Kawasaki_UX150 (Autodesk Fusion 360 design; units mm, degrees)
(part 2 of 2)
sketch "Esquisse42" plane through (0, 0, 1860) normal (0, 0, -1) x axis (1, 0, 0)
  line L1 (435, 100) -> (517.3223, 17.6777)
  line L2 (235, 100) -> (435, 100)
  line L3 (152.6777, 17.6777) -> (235, 100)
  line L4 (281.967, -146.967) -> (152.6777, -17.6777)
  line L5 (517.3223, -17.6777) -> (388.033, -146.967)
  line L6 (335, -210) -> (335, 100)
  line L7 (270, -210) -> (335, -210)
  line L8 (400, -210) -> (270, -210)
  line L9 (400, -135) -> (400, -210)
  line L10 (270, -135) -> (400, -135)
  line L11 (270, -210) -> (270, -135)
  line L12 (270, -135) -> (400, -135)
  line L13 (270, -190) -> (270, -135)
  line L14 (400, -190) -> (270, -190)
  line L15 (400, -135) -> (400, -190)
  arc A1 centre (170.3553, 0) radius 25 clockwise from (152.6777, -17.6777) to (152.6777, 17.6777)
  arc A2 centre (335, -93.934) radius 75 clockwise from (388.033, -146.967) to (281.967, -146.967)
  arc A3 centre (499.6447, 0) radius 25 clockwise from (517.3223, 17.6777) to (517.3223, -17.6777)
  point P13 (335, 100)
  point P17 (400, -135)
  point P20 (270, -190)
  point P15 (270, -210)
  point P16 (400, -210)
  midpoint L2 P13
  perpendicular L2 L6
  perpendicular L6 L7
  horizontal L8
  vertical L9
  horizontal L10
  vertical L11
  coincident L5 P17
  horizontal L12
  vertical L13
  horizontal L14
  vertical L15
  coincident L11 P20
  dimension "d247" distance P15 P16 = 130
extrude "Extrusion72" add sketch "Esquisse42" profile of L4 A2 L5 L6 L9 L11 L13 L14 L15 against normal blind 20
sketch "Esquisse43" plane through (0, 0, 1980) normal (0, 0, 1) x axis (-1, 0, 0)
  line L1 (-517.3223, 17.6777) -> (-435, 100)
  line L2 (-388.033, -146.967) -> (-517.3223, -17.6777)
  line L3 (-152.6777, -17.6777) -> (-281.967, -146.967)
  line L4 (-235, 100) -> (-152.6777, 17.6777)
  line L5 (-435, 100) -> (-235, 100)
  line L6 (-335, 0) -> (-335, 100)
  line L7 (-460, -70) -> (-210, -70)
  line L8 (-460, 100) -> (-460, -70)
  line L9 (-210, 100) -> (-460, 100)
  line L10 (-210, -70) -> (-210, 100)
  line L11 (-220, -70) -> (-291.2116, -146.0192)
  line L12 (-450, -70) -> (-378.7884, -146.0192)
  arc A1 centre (-499.6447, 0) radius 25 clockwise from (-517.3223, -17.6777) to (-517.3223, 17.6777)
  arc A2 centre (-335, -93.934) radius 75 clockwise from (-281.967, -146.967) to (-388.033, -146.967)
  arc A3 centre (-170.3553, 0) radius 25 clockwise from (-152.6777, 17.6777) to (-152.6777, -17.6777)
  circle C1 centre (-335, 0) radius 105
  circle C2 centre (-460, 0) radius 45
  circle C3 centre (-210, 0) radius 45
  circle C4 centre (-335, -105) radius 60
  point P13 (-335, 100)
  point P14 (-335, 0)
  point P15 (-335, 0)
  point P20 (-460, 0)
  point P21 (-210, 0)
  point P22 (-335, -105)
  point P23 (-291.2116, -146.0192)
  point P24 (-220, -70)
  point P25 (-378.7884, -146.0192)
  point P26 (-450, -70)
  midpoint L5 P13
  perpendicular L5 L6
  coincident P14 P15
  horizontal L7
  vertical L8
  horizontal L9
  vertical L10
  coincident L8 P20
  coincident L10 P21
  coincident C1 P22
  coincident C4 P23
  tangent C4 L11
  coincident L7 P24
  coincident C4 P25
  tangent C4 L12
  coincident L7 P26
  dimension "d250" diameter C2 = 90
  dimension "d251" diameter C3 = 90
  dimension "d252" diameter C4 = 120
extrude "Extrusion73" cut sketch "Esquisse43" profile of L1 A1 L2 A2 L3 A3 L4 L7 L8 L10 C2 C3 C4 L11 L12 against normal blind 100
sketch "Esquisse44" plane through (335, 0, 0) normal (1, 0, 0) x axis (0, 1, 0)
  line L1 (0, 3220) -> (0, 0)
  line L2 (0, 3030) -> (0, 3220)
  line L3 (0, 3010) -> (0, 3220)
  line L4 (-100, 3010) -> (0, 3010)
  line L5 (-100, 2930) -> (-100, 3010)
  line L6 (-80, 2910) -> (-100, 2930)
  line L7 (0, 2910) -> (-80, 2910)
  line L8 (-70, 2910) -> (0, 2910)
  line L9 (-75, 1975) -> (0, 1975)
  line L10 (-70, 2910) -> (-75, 1975)
  line L11 (-70, 3050) -> (0, 3050)
  line L12 (-70, 3025) -> (-70, 3050)
  line L13 (-95, 3025) -> (-70, 3025)
  line L14 (-100, 3020) -> (-95, 3025)
  line L15 (-100, 3010) -> (-100, 3020)
  line L16 (75, 1975) -> (0, 1975)
  line L17 (70, 2910) -> (0, 2910)
  line L18 (70, 2910) -> (75, 1975)
  line L19 (-100, 2000) -> (0, 2000)
  line L20 (-100, 1980) -> (-100, 2000)
  line L21 (0, 1980) -> (-100, 1980)
  line L22 (99.9986, 2000.5348) -> (0, 2000)
  point P1 (0, 0)
  point P2 (0, 0)
  point P4 (0, 3030)
  point P5 (0, 3010)
  point P9 (0, 2910)
  point P10 (-70, 2910)
  point P11 (0, 1975)
  point P13 (0, 3050)
  point P20 (0, 2000)
  point P23 (0, 1980)
  point P3 (0, 3220)
  point P19 (70, 2910)
  point P24 (99.9986, 2000.5348)
  coincident P1 P2
  vertical L1
  coincident L1 P4
  coincident L1 P5
  perpendicular L1 L4
  perpendicular L4 L5
  coincident L1 P9
  perpendicular L1 L7
  coincident L7 P10
  coincident L1 P11
  perpendicular L1 L9
  coincident L3 P13
  perpendicular L3 L11
  perpendicular L11 L12
  perpendicular L12 L13
  perpendicular L4 L15
  perpendicular L1 L16
  perpendicular L1 L17
  coincident L1 P20
  perpendicular L1 L19
  perpendicular L17 L20
  coincident L1 P23
  perpendicular L1 L21
  perpendicular L18 L22
  dimension "d255" distance P2 P3 = 3220 (= "700 mm + 900 mm + 270 mm + 1350 mm")
  dimension "d257" distance P9 P19 = 70
  dimension "d258" distance P20 P24 = 100
revolve "Révolution5" sketch "Esquisse44" AlongAngle 360
revolve "Révolution6" sketch "Esquisse44" AlongAngle 360
sketch "Esquisse45" plane through (0, 0, 1980) normal (0, 0, 1) x axis (-1, 0, 0)
  line L1 (-460, 45) -> (-460, 75)
  line L2 (-460, -70) -> (-460, -45)
  line L3 (-450, -70) -> (-460, -70)
  line L4 (-378.7884, -146.0192) -> (-450, -70)
  line L5 (-220, -70) -> (-291.2116, -146.0192)
  line L6 (-210, -70) -> (-220, -70)
  line L7 (-210, -45) -> (-210, -70)
  line L8 (-210, 75) -> (-210, 45)
  line L9 (-235, 100) -> (-210, 75)
  line L10 (-335, 100) -> (-235, 100)
  line L11 (-435, 100) -> (-335, 100)
  line L12 (-460, 75) -> (-435, 100)
  line L13 (-235, 100) -> (-235, 0)
  line L14 (-435, 0) -> (-435, 100)
  arc A1 centre (-460, 0) radius 45 clockwise from (-460, -45) to (-460, 45)
  arc A2 centre (-335, -105) radius 60 clockwise from (-291.2116, -146.0192) to (-378.7884, -146.0192)
  arc A3 centre (-210, 0) radius 45 clockwise from (-210, 45) to (-210, -45)
  circle C1 centre (-335, 0) radius 100
  point P21 (-235, 0)
  point P17 (-235, 100)
  point P22 (-235, 100)
  point P20 (-435, 100)
  point P23 (-435, 100)
  point P24 (-435, 0)
  coincident C1 P21
  tangent C1 L13
  coincident P17 P22
  coincident P20 P23
  coincident C1 P24
  tangent C1 L14
extrude "Extrusion74" cut sketch "Esquisse45" profile of L1 A1 L2 L3 L4 A2 L5 L6 L7 A3 L8 L9 C1 L12 L13 L14 against normal blind 50
extrude "Extrusion75" cut of existing geometry blind -10
sketch "Esquisse46" plane through (0, 0, 1860) normal (0, 0, -1) x axis (1, 0, 0)
  line L1 (435, 100) -> (517.3223, 17.6777)
  line L2 (235, 100) -> (435, 100)
  line L3 (152.6777, 17.6777) -> (235, 100)
  line L4 (270, -135) -> (152.6777, -17.6777)
  line L5 (270, -190) -> (270, -135)
  line L6 (400, -190) -> (270, -190)
  line L7 (400, -135) -> (400, -190)
  line L8 (517.3223, -17.6777) -> (400, -135)
  line L9 (335, 90) -> (335, 100)
  line L10 (335, 0) -> (335, 90)
  line L11 (535, 0) -> (400, -135)
  line L12 (460.7538, -74.2462) -> (535, 0)
  line L13 (368.8299, -17.6777) -> (425.3984, -74.2462)
  line L14 (425.3984, 74.2462) -> (368.8299, 17.6777)
  line L15 (460.7538, 74.2462) -> (535, 0)
  arc A1 centre (170.3553, 0) radius 25 clockwise from (152.6777, -17.6777) to (152.6777, 17.6777)
  arc A2 centre (499.6447, 0) radius 25 clockwise from (517.3223, 17.6777) to (517.3223, -17.6777)
  circle C1 centre (335, 0) radius 25
  arc A3 centre (443.0761, -56.5685) radius 25 clockwise from (460.7538, -74.2462) to (425.3984, -74.2462)
  arc A4 centre (386.5076, 0) radius 25 clockwise from (368.8299, -17.6777) to (368.8299, 17.6777)
  arc A5 centre (443.0761, 56.5685) radius 25 clockwise from (425.3984, 74.2462) to (460.7538, 74.2462)
  circle C2 centre (443.0761, 0) radius 50
  point P14 (335, 100)
  point P16 (335, 0)
  point P17 (335, 0)
  point P11 (400, -135)
  point P18 (400, -135)
  point P20 (443.0761, -91.9239)
  point P21 (351.1522, 0)
  point P19 (535, 0)
  midpoint L2 P14
  perpendicular L2 L9
  perpendicular L2 L10
  coincident P16 P17
  coincident P11 P18
  parallel L8 L11
  parallel L11 L12
  perpendicular L8 L13
  perpendicular L13 L14
  perpendicular L14 L15
  coincident P20 L12
  coincident P20 L13
  tangent L12 A3
  tangent L13 A3
  coincident P21 L13
  coincident P21 L14
  tangent L13 A4
  tangent L14 A4
  equal A3 A4
  tangent L14 A5
  tangent L15 A5
  equal A3 A5
  dimension "d264" distance P19 P20 = 130
  dimension "d265" distance P20 P21 = 130
  dimension "d266" radius A3 = 25
  dimension "d267" diameter C2 = 100
extrude "Extrusion76" new body sketch "Esquisse46" profile of C2 along normal blind 220
extrude "Extrusion77" add sketch "Esquisse46" profile of L1 L8 A2 L11 L12 L13 L14 L15 A3 A4 A5 C2 along normal blind 170
circular_pattern "Réseau C" TotalAngle 180
combine "Combiner11"
sketch "Esquisse47" plane through (0, 0, 0) normal (1, 0, 0) x axis (0, 1, 0)
  line L1 (-200, 1660) -> (-120, 1660)
  line L2 (-200, 1750) -> (-200, 1660)
  line L3 (-170, 1780) -> (-200, 1750)
  line L4 (-170, 1830) -> (-170, 1780)
  line L5 (190.7691, 1975) -> (-25, 1975)
  line L6 (190.7691, 1920) -> (190.7691, 1975)
  line L7 (-35, 1920) -> (190.7691, 1920)
  line L8 (-120, 1660) -> (-120, 1835)
  arc A1 centre (-35, 1835) radius 85 clockwise from (-120, 1835) to (-35, 1920)
  arc A2 centre (-25, 1830) radius 145 clockwise from (-170, 1830) to (-25, 1975)
  horizontal L1
  perpendicular L1 L2
  parallel L2 L4
  perpendicular L4 L5
  perpendicular L5 L6
  perpendicular L6 L7
  perpendicular L1 L8
  tangent L7 A1
  tangent L8 A1
  tangent L5 A2
  tangent L4 A2
  dimension "d274" radius A1 = 85
  dimension "d275" radius A2 = 145
extrude "Extrusion78" new body sketch "Esquisse47" against normal blind 400
extrude "Extrusion79" add of existing geometry blind 200
sketch "Esquisse48" plane through (0, 0, 0) normal (0, 0, 1) x axis (1, 0, 0)
  line L1 (-100, -125) -> (0, -150)
  line L2 (-200, -125) -> (-100, -125)
  line L3 (-200, 175) -> (-200, -125)
  line L4 (-175, 200) -> (-200, 175)
  line L5 (-175, 275) -> (-175, 200)
  line L6 (-250, 275) -> (-175, 275)
  line L7 (-250, -175) -> (-250, 275)
  line L8 (-150, -175) -> (-250, -175)
  line L9 (-100, -190) -> (-150, -175)
  line L10 (0, -190) -> (-100, -190)
  line L11 (0, -150) -> (0, -190)
  horizontal L2
  perpendicular L2 L3
  perpendicular L2 L5
  perpendicular L3 L6
  perpendicular L6 L7
  perpendicular L7 L8
  perpendicular L7 L10
  perpendicular L10 L11
extrude "Extrusion80" new body sketch "Esquisse48" along normal blind 2500
sketch "Esquisse49" plane through (0, 0, 0) normal (0, 1, 0) x axis (1, 0, 0)
  line L1 (-240, -1800) -> (-240, -1990)
  line L2 (-240, -1830) -> (-240, -1800)
  line L3 (0, -1660) -> (-70, -1660)
  line L4 (0, -1780) -> (0, -1660)
  line L5 (-110, -1780) -> (0, -1780)
  line L6 (-200, -1780) -> (-190, -1780)
  line L7 (-200, -1990) -> (-200, -1870)
  line L8 (-240, -1990) -> (-200, -1990)
  arc A1 centre (-70, -1830) radius 170 clockwise from (-240, -1830) to (-70, -1660)
  arc A2 centre (-110, -1870) radius 90 clockwise from (-200, -1870) to (-110, -1780)
  point P6 (-190, -1780)
  point P7 (-200, -1780)
  vertical L1
  parallel L1 L2
  perpendicular L2 L3
  perpendicular L3 L4
  perpendicular L4 L5
  perpendicular L4 L6
  perpendicular L6 L7
  perpendicular L1 L8
  tangent L3 A1
  tangent L2 A1
  coincident P6 L5
  coincident P7 L7
  tangent L5 A2
  tangent L7 A2
  dimension "d282" radius A1 = 170
  dimension "d283" radius A2 = 90
extrude "Extrusion81" new body sketch "Esquisse49" profile of L1 L3 L4 L5 L7 L8 A1 A2 along normal blind 600
extrude "Extrusion82" add of existing geometry blind 700
combine "Combiner12"
combine "Combiner13"
sketch "Esquisse50" plane through (0, 0, 1975) normal (0, 0, 1) x axis (-1, 0, 0)
  line L1 (240, 25) -> (240, -190.7691)
  line L2 (200, 25) -> (240, 25)
  line L3 (200, -190.7691) -> (200, 25)
  line L4 (240, -190.7691) -> (200, -190.7691)
  line L5 (70, -190.7691) -> (240, -190.7691)
  line L6 (70, -340) -> (70, -190.7691)
  line L7 (240, -340) -> (70, -340)
  line L8 (240, -190.7691) -> (240, -340)
  line L9 (240, -270) -> (240, -340)
  line L10 (170, -340) -> (240, -340)
  line L11 (240, -270) -> (170, -340)
  line L12 (174.7349, -205.2651) -> (200, -180)
  line L13 (70, -205.2651) -> (174.7349, -205.2651)
  point P2 (240, -190.7691)
  point P6 (240, -190.7691)
  point P10 (240, -270)
  point P11 (170, -340)
  point P12 (200, -180)
  point P14 (70, -205.2651)
  horizontal L5
  vertical L6
  horizontal L7
  vertical L8
  coincident P2 P6
  coincident L8 P10
  coincident L7 P11
  coincident L3 P12
  parallel L11 L12
  coincident L6 P14
  perpendicular L6 L13
extrude "Extrusion83" add sketch "Esquisse50" profile of L4 L5 L6 L7 L8 L11 L12 L13 against normal blind 60
sketch "Esquisse51" plane through (0, 0, 1975) normal (0, 0, 1) x axis (-1, 0, 0)
  line L1 (240, 25) -> (240, -270)
  line L2 (200, 25) -> (240, 25)
  line L3 (200, -190.7691) -> (200, 25)
  line L4 (189.2309, -190.7691) -> (200, -190.7691)
  line L5 (174.7349, -205.2651) -> (189.2309, -190.7691)
  line L6 (70, -205.2651) -> (174.7349, -205.2651)
  line L7 (70, -340) -> (70, -205.2651)
  line L8 (170, -340) -> (70, -340)
  line L9 (240, -270) -> (170, -340)
  line L10 (-380, -230) -> (70, -230)
  line L11 (-380, -330) -> (-380, -230)
  line L12 (70, -330) -> (-380, -330)
  line L13 (70, -230) -> (70, -330)
  line L14 (-290, -330) -> (-380, -330)
  line L15 (-290, -190) -> (-290, -330)
  line L16 (-380, -190) -> (-290, -190)
  line L17 (-380, -330) -> (-380, -190)
  line L18 (-310, -330) -> (-380, -330)
  line L19 (-310, -230) -> (-310, -330)
  line L20 (-380, -230) -> (-310, -230)
  line L21 (-380, -330) -> (-380, -230)
  point P11 (70, -230)
  point P19 (-310, -230)
  horizontal L10
  vertical L11
  horizontal L12
  vertical L13
  coincident L7 P11
  horizontal L14
  vertical L15
  horizontal L16
  vertical L17
  horizontal L18
  vertical L19
  horizontal L20
  vertical L21
  coincident L10 P19
extrude "Extrusion84" add sketch "Esquisse51" profile of L10 L11 L12 L14 L15 L16 L17 L18 L19 L20 L21 against normal blind 125
extrude "Extrusion85" cut of existing geometry blind -75
extrude "Extrusion86" cut of existing geometry blind -10
extrude "Extrusion87" cut sketch "Esquisse51" profile of L10 L15 L16 L17 L20 against normal blind 105
extrude "Extrusion88" add of existing geometry blind 75
sketch "Esquisse52" plane through (0, 0, 0) normal (0, 1, 0) x axis (1, 0, 0)
  line L1 (0, -3220) -> (0, 0)
  line L2 (335, -3220) -> (0, -3220)
  line L3 (335, -3425) -> (335, -3220)
  line L4 (245, -3425) -> (335, -3425)
  line L5 (245, -3269.0535) -> (245, -3425)
  line L6 (245, -3322.5) -> (335, -3322.5)
  circle C1 centre (335, -3220) radius 102.5
  circle C2 centre (335, -3220) radius 87.5
  circle C3 centre (335, -3220) radius 65
  circle C4 centre (335, -3220) radius 45
  point P1 (0, 0)
  point P2 (0, 0)
  point P4 (335, -3220)
  point P5 (335, -3220)
  point P9 (335, -3220)
  point P12 (245, -3269.0535)
  point P13 (335, -3322.5)
  point P14 (245, -3322.5)
  point P3 (0, -3220)
  point P10 (335, -3425)
  point P11 (245, -3425)
  coincident P1 P2
  vertical L1
  perpendicular L1 L2
  coincident P4 P5
  concentric C1 C2
  concentric C1 C3
  concentric C2 C4
  coincident P5 P9
  perpendicular L2 L3
  perpendicular L3 L4
  coincident C1 P12
  perpendicular L2 L5
  midpoint L3 P13
  coincident L5 P14
  tangent C1 L6
  perpendicular L5 L6
  dimension "d300" distance P2 P3 = 3220
  dimension "d301" distance P3 P4 = 335
  dimension "d302" diameter C1 = 205
  dimension "d303" diameter C2 = 175
  dimension "d304" diameter C3 = 130
  dimension "d305" diameter C4 = 90
  dimension "d320" distance P9 P10 = 205
  dimension "d321" distance P10 P11 = 90
extrude "Extrusion89" new body sketch "Esquisse52" profile of C4 against normal blind 150
extrude "Extrusion90" add sketch "Esquisse52" profile of C3 C4 against normal blind 140
extrude "Extrusion91" add sketch "Esquisse52" profile of C2 C3 against normal blind 130
extrude "Extrusion92" add sketch "Esquisse52" profile of C1 C2 against normal blind 110
extrude "Extrusion93" cut of existing geometry blind -70
extrude "Extrusion94" add sketch "Esquisse52" profile of C3 C4 against normal blind 70
extrude "Extrusion95" cut sketch "Esquisse52" profile of C3 C4 against normal blind 40
revolve "Révolution7" sketch "Esquisse52" AlongAngle 360
sketch "Esquisse53" plane through (335, 0, 0) normal (1, 0, 0) x axis (0, 1, 0)
  line L1 (0, 3180) -> (0, 3050)
  line L2 (40, 3180) -> (0, 3180)
  line L3 (40, 3050) -> (40, 3180)
  line L4 (0, 3050) -> (40, 3050)
  vertical L1
  perpendicular L1 L2
  perpendicular L2 L3
  perpendicular L1 L4
revolve "Révolution8" sketch "Esquisse53" AlongAngle 360
work_plane "Plan de construction2" sketch "Esquisse52" AlongDistance 50
cylinder_primitive "CylindrePrimitive" Height 40 Diameter 150
sketch "Esquisse55" plane through (0, 90, 0) normal (0, 1, 0) x axis (-1, 0, 0)
  line L1 (-425, 3345) -> (-335, 3345)
  line L2 (-425, 3288.589) -> (-425, 3345)
  line L3 (-245, 3345) -> (-335, 3345)
  line L4 (-245, 3288.589) -> (-245, 3345)
  line L5 (-245, 3345) -> (-425, 3345)
  line L6 (-245, 3370) -> (-245, 3345)
  line L7 (-425, 3370) -> (-245, 3370)
  line L8 (-425, 3345) -> (-425, 3370)
  line L9 (-395, 3370) -> (-335, 3370)
  line L10 (-395, 3265) -> (-395, 3370)
  line L11 (-275, 3370) -> (-335, 3370)
  line L12 (-275, 3265) -> (-275, 3370)
  circle C1 centre (-335, 3220) radius 75
  circle C2 centre (-335, 3245) radius 100
  point P4 (-335, 3345)
  point P6 (-425, 3288.589)
  point P8 (-245, 3288.589)
  point P12 (-335, 3370)
  point P14 (-395, 3265)
  point P16 (-275, 3265)
  point P5 (-425, 3345)
  point P7 (-245, 3345)
  point P9 (-245, 3345)
  point P11 (-425, 3370)
  point P13 (-395, 3370)
  point P15 (-275, 3370)
  coincident C2 P4
  horizontal L1
  coincident C2 P6
  perpendicular L1 L2
  perpendicular L2 L3
  coincident C2 P8
  perpendicular L1 L4
  horizontal L5
  vertical L6
  horizontal L7
  vertical L8
  midpoint L7 P12
  parallel L7 L9
  coincident C1 P14
  perpendicular L7 L10
  perpendicular L10 L11
  coincident C1 P16
  perpendicular L7 L12
  dimension "d327" diameter C2 = 200
  dimension "d328" distance P4 P5 = 90
  dimension "d329" distance P4 P7 = 90
  dimension "d330" distance P5 P9 = 180
  dimension "d331" distance P5 P11 = 25
  dimension "d332" distance P12 P13 = 60
  dimension "d333" distance P12 P15 = 60
extrude "Extrusion96" add sketch "Esquisse55" profile of C1 C2 L1 L3 L5 L7 L9 L10 L11 L12 against normal blind 40
sketch "Esquisse56" plane through (0, -110, 0) normal (0, -1, 0) x axis (1, 0, 0)
  line L1 (425, 3322.5) -> (335, 3322.5)
  line L2 (425, 3269.0535) -> (425, 3322.5)
  line L3 (245, 3322.5) -> (425, 3322.5)
  line L4 (245, 3342.5) -> (245, 3322.5)
  line L5 (425, 3342.5) -> (245, 3342.5)
  line L6 (425, 3322.5) -> (425, 3342.5)
  line L7 (245, 3269.0535) -> (245, 3322.5)
  circle C1 centre (335, 3220) radius 87.5
  circle C2 centre (335, 3220) radius 102.5
  point P3 (335, 3322.5)
  point P5 (425, 3269.0535)
  point P9 (245, 3269.0535)
  point P4 (425, 3322.5)
  point P6 (245, 3322.5)
  point P8 (425, 3342.5)
  coincident C2 P3
  tangent C2 L1
  horizontal L1
  coincident C2 P5
  perpendicular L1 L2
  horizontal L3
  vertical L4
  horizontal L5
  vertical L6
  coincident C2 P9
  perpendicular L3 L7
  dimension "d336" distance P3 P4 = 90
  dimension "d337" distance P4 P6 = 180
  dimension "d338" distance P4 P8 = 20
extrude "Extrusion97" add sketch "Esquisse56" profile of C2 L1 L2 L3 L4 L5 L6 L7 against normal blind 40
extrude "Extrusion98" add of existing geometry blind 10
extrude "Extrusion99" add of existing geometry blind 10
split "Scinder1"
extrude "Extrusion100" cut of existing geometry blind -30
extrude "Extrusion101" new body sketch "Esquisse52" profile of L2 C4 L3 against normal blind 70
extrude "Extrusion102" add sketch "Esquisse52" profile of L2 C4 L3 along normal blind 40
extrude "Extrusion103" add of existing geometry blind 90
extrude "Extrusion104" add of existing geometry blind 10
split "Scinder2"
component_from_bodies "Corps->Comp1"
combine "Combiner14"
component_from_bodies "Corps->Comp2"
ground "Fixer"
joint "Assembler1" alignAngle 0 alignOffsetX 0 alignOffsetY 0 alignOffsetZ 0 RotationMinimum -180 RotationMaximum 180
component_from_bodies "Corps->Comp3"
joint "Assembler2" alignAngle -0.035 alignOffsetX 0 alignOffsetY 0 alignOffsetZ 0 RotationMinimum -70 RotationMaximum 65
component_from_bodies "Corps->Comp4"
joint "Assembler3" alignAngle -1 alignOffsetX 0 alignOffsetY 0 alignOffsetZ 0 RotationMinimum -65 RotationMaximum 70
component_from_bodies "Corps->Comp5"
joint "Assembler4" alignAngle 0 alignOffsetX 0 alignOffsetY 0 alignOffsetZ 0
joint "Assembler5" alignAngle 0 alignOffsetX 0 alignOffsetY 0 alignOffsetZ 0
component_from_bodies "Corps->Comp6"
joint "Assembler6" alignAngle -90 alignOffsetX 0 alignOffsetY 0 alignOffsetZ 0 RotationMinimum -119 RotationMaximum 90
component_from_bodies "Corps->Comp7"
as_built_joint "Réelle"
component_from_bodies "Corps->Comp8"
joint "Assembler7" alignAngle 0 alignOffsetX 0 alignOffsetY 0 alignOffsetZ 0
extrude "Extrusion105" cut of existing geometry blind -20
sketch "Esquisse57" plane through (0, 0, 3405) normal (0, 0, 1) x axis (-1, 0, 0)
  circle C1 centre (-335, 0) radius 90
  circle C2 centre (-335, 0) radius 75
  concentric C1 C2
extrude "Extrusion106" add sketch "Esquisse57" profile of C2 along normal blind 10
sketch "Esquisse58" plane through (0, 0, 3415) normal (0, 0, 1) x axis (-1, 0, 0)
  circle C1 centre (-335, 0) radius 75
  circle C2 centre (-335, 0) radius 85
  concentric C1 C2
extrude "Extrusion107" new body sketch "Esquisse58" along normal blind 10
component_from_bodies "Corps->Comp9"
component_from_bodies "Corps->Comp10"
joint "Assembler8" alignAngle 0 alignOffsetX 0 alignOffsetY 0 alignOffsetZ 0
joint "Assembler9" alignAngle 0 alignOffsetX 0 alignOffsetY 0 alignOffsetZ 0 RotationMinimum -125 RotationMaximum 125
work_plane "Plan de construction3" AlongDistance 2100
sketch "Esquisse59" plane through (0, 0, 2100) normal (0, 0, 1) x axis (1, 0, 0)
  line L1 (550, -250) -> (250, -350)
  line L2 (550, -400) -> (550, -250)
  line L3 (250, -400) -> (550, -400)
  line L4 (250, -350) -> (250, -400)
  vertical L2
  perpendicular L2 L3
  perpendicular L3 L4
split "Scinder1"
combine "Combiner1"
extrude "Extrusion1" cut of existing geometry blind -70
extrude "Extrusion2" cut sketch "Esquisse59" against normal blind 550
extrude "Extrusion3" add of existing geometry blind 70
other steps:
base_feature "Fonction de base1"
base_feature "Fonction de base1"
base_feature "Fonction de base1"
base_feature "Fonction de base1"
base_feature "Fonction de base1"
base_feature "Fonction de base1"
base_feature "Fonction de base1"
base_feature "Fonction de base1"
base_feature "Fonction de base1"
base_feature "Fonction de base1"
create_component "CreateComponent1"
remove_body "RemoveBody2"
create_component "CreateComponent2"
remove_body "RemoveBody3"
joint_origin "JointOrigin1"
joint_origin "JointOrigin1"
create_component "CreateComponent3"
remove_body "RemoveBody4"
create_component "CreateComponent4"
remove_body "RemoveBody5"
create_component "CreateComponent5"
remove_body "RemoveBody6"
create_component "CreateComponent6"
remove_body "RemoveBody7"
joint_origin "JointOrigin1"
joint_origin "JointOrigin3"
create_component "CreateComponent7"
remove_body "RemoveBody8"
create_component "CreateComponent8"
remove_body "RemoveBody9"
joint_origin "JointOrigin1"
joint_origin "JointOrigin2"
create_component "CreateComponent9"
remove_body "RemoveBody10"
create_component "CreateComponent10"
remove_body "RemoveBody11"
joint_origin "JointOrigin1"
joint_origin "JointOrigin1"
joint_origin "JointOrigin2"
joint_origin "JointOrigin2"
joint_origin "JointOrigin5"
joint_origin "JointOrigin7"
joint_origin "JointOrigin6"
joint_origin "JointOrigin6"
joint_origin "JointOrigin7"
joint_origin "JointOrigin7"
joint_origin "JointOrigin10"
joint_origin "JointOrigin12"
